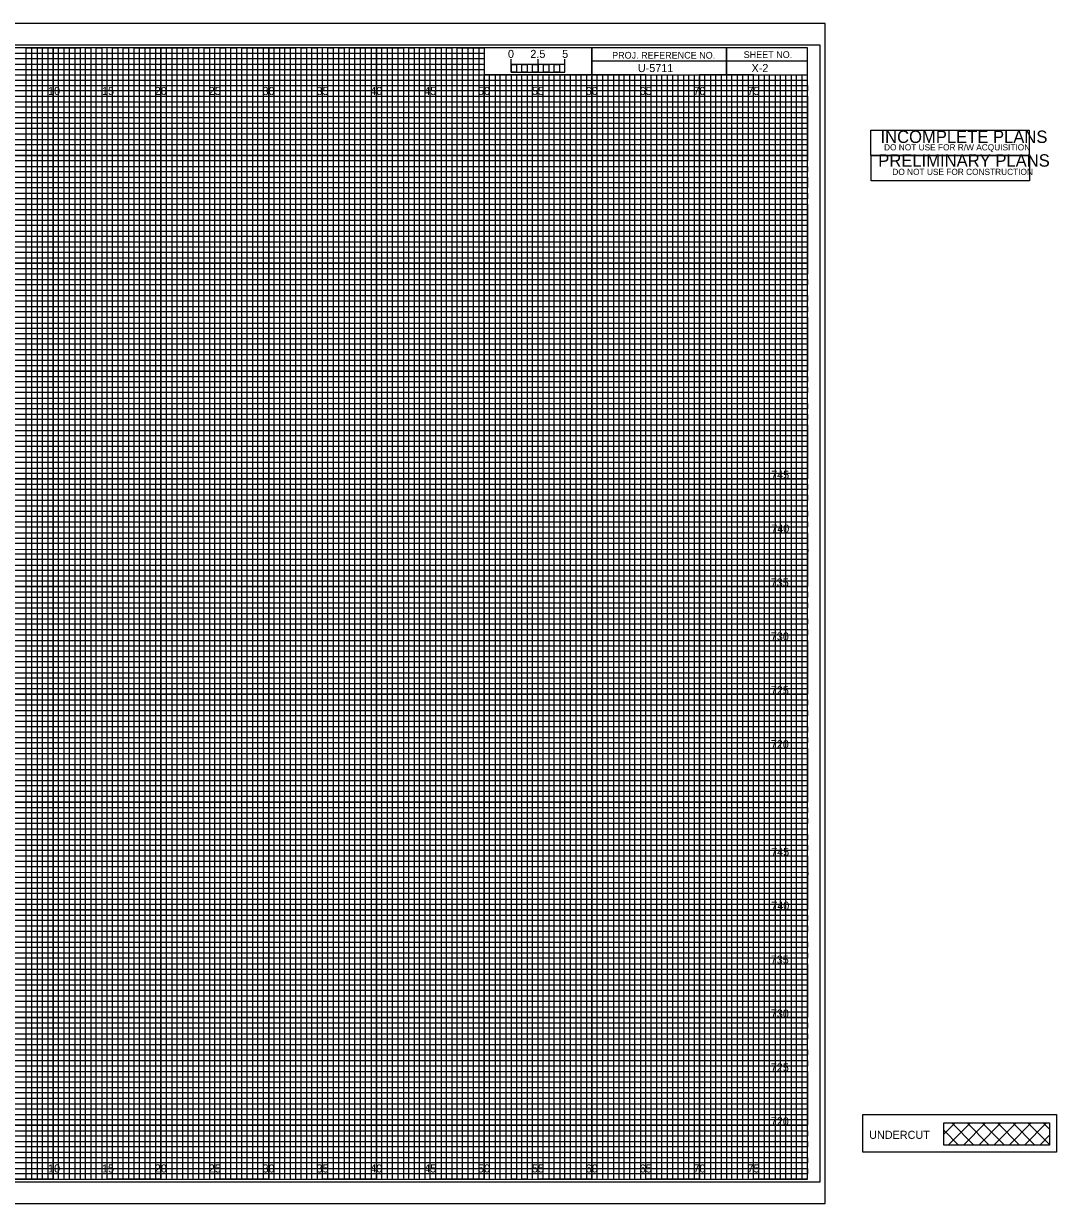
# Model space of a CAD drawing. Extents: x -7 to 183, y -2 to 107.
# Drawn here: x 87.2 to 183.1, y -2.2 to 107.2 of the extents above; entities that cross this region are included whole.
import ezdxf

# ---------------------------------------------------------------- set-up
doc = ezdxf.new("R2010")
doc.units = 0
for name, color, linetype in [('Prop Grid Mask', 7, 'Continuous'), ('Prop Road Sect_ Recs - UC (Outline)', 7, 'Continuous'), ('Prop VPI Label', 7, 'Continuous'), ('Prop XS Bar Scale Labels', 7, 'Continuous'), ('Prop XS Elevation Labels', 7, 'Continuous'), ('Prop XS Offset Labels', 7, 'Continuous'), ('Prop XS Project Number', 7, 'Continuous'), ('Prop XS Sheet Number', 7, 'Continuous'), ('Sheet Cross Section CELL', 7, 'Continuous'), ('Sheet Cross Section Grid Major CELL', 7, 'Continuous'), ('Sheet Cross Section Grid Middle CELL', 7, 'Continuous'), ('Sheet Cross Section Grid Minor 1 CELL', 7, 'Continuous'), ('Sheet Cross Section Grid Minor 2 CELL', 7, 'Continuous'), ('Sheet Cross Section Scale CELL', 7, 'Continuous'), ('Sheet Cutting Line CELL', 7, 'Continuous'), ('Sheet DOT Grid CELL', 7, 'Continuous'), ('Sheet Plot Border Inside CELL', 7, 'Continuous'), ('Sheet Plot Border Outside CELL', 7, 'Continuous'), ('Sheet Sticker Incomplete CELL', 7, 'Continuous'), ('Sheet Sticker Preliminary CELL', 7, 'Continuous')]:
    doc.layers.add(name, color=color, linetype=linetype)

msp = doc.modelspace()

# ---------------------------------------------------------------- linework, layer by layer
at = {"layer": 'Prop Grid Mask'}
msp.add_lwpolyline([(165.14, 5.99), (183.12, 5.99), (183.12, 2.5), (165.14, 2.5)], close=True, dxfattribs=at)
at = {"layer": 'Prop Road Sect_ Recs - UC (Outline)'}
for p, q in [((172.66, 4.17), (173.71, 5.22)), ((172.66, 4.56), (174.04, 3.17)), ((173.08, 3.17), (175.13, 5.22)), ((173.41, 5.22), (175.46, 3.17)), ((174.49, 3.17), (176.54, 5.22)), ((174.83, 5.22), (176.87, 3.17)), ((175.91, 3.17), (177.95, 5.22)), ((176.24, 5.22), (178.29, 3.17)), ((177.32, 3.17), (179.37, 5.22)), ((177.65, 5.22), (179.7, 3.17)), ((178.74, 3.17), (180.78, 5.22)), ((179.07, 5.22), (181.11, 3.17)), ((180.15, 3.17), (182.2, 5.22)), ((180.48, 5.22), (182.47, 3.23)), ((181.9, 5.22), (182.47, 4.64)), ((181.57, 3.17), (182.47, 4.08))]:
    msp.add_line(p, q, dxfattribs=at)
msp.add_lwpolyline([(172.66, 5.22), (182.47, 5.22), (182.47, 3.17), (172.66, 3.17)], close=True, dxfattribs=at)
at = {"layer": 'Sheet Cross Section CELL'}
for p, q in [((152.5, 105), (152.5, 102.5)), ((152.5, 102.5), (152.5, 105)), ((160, 103.75), (140, 103.75)), ((140, 103.75), (140, 102.5)), ((140, 102.5), (160, 102.5))]:
    msp.add_line(p, q, dxfattribs=at)
for points in [[(160, 105), (0, 105), (0, 0), (160, 0)], [(140, 105), (130, 105), (130, 102.52), (140, 102.52)], [(160, 105), (140, 105), (140, 102.5), (160, 102.5)]]:
    msp.add_lwpolyline(points, close=True, dxfattribs=at)
at = {"layer": 'Sheet Cross Section Grid Major CELL'}
for p, q in [((95, 105), (90, 105)), ((90, 105), (90, 0)), ((95, 0), (95, 105)), ((105, 105), (100, 105)), ((100, 105), (100, 0)), ((105, 0), (105, 105)), ((115, 105), (110, 105)), ((110, 105), (110, 0)), ((115, 0), (115, 105)), ((125, 105), (120, 105)), ((120, 105), (120, 0)), ((125, 0), (125, 105)), ((130, 105), (130, 0)), ((135, 0), (135, 102.5)), ((145, 102.5), (140, 102.5)), ((140, 102.5), (140, 0)), ((145, 0), (145, 102.5)), ((155, 102.5), (150, 102.5)), ((150, 102.5), (150, 0)), ((155, 0), (155, 102.5)), ((90, 0), (85, 0)), ((100, 0), (95, 0)), ((110, 0), (105, 0)), ((120, 0), (115, 0)), ((130, 0), (125, 0)), ((140, 0), (135, 0)), ((150, 0), (145, 0)), ((160, 0), (155, 0)), ((160, 0), (160, 0))]:
    msp.add_line(p, q, dxfattribs=at)
for points in [[(0, 100), (160, 100), (160, 95), (0, 95)], [(0, 90), (160, 90), (160, 85), (0, 85)], [(0, 80), (160, 80), (160, 75), (0, 75)], [(0, 70), (160, 70), (160, 65), (0, 65)], [(0, 60), (160, 60), (160, 55), (0, 55)], [(0, 50), (160, 50), (160, 45), (0, 45)], [(0, 40), (160, 40), (160, 35), (0, 35)], [(0, 30), (160, 30), (160, 25), (0, 25)], [(0, 20), (160, 20), (160, 15), (0, 15)], [(0, 10), (160, 10), (160, 5), (0, 5)]]:
    msp.add_lwpolyline(points, dxfattribs=at)
at = {"layer": 'Sheet Cross Section Grid Middle CELL'}
for points in [[(82.5, 0), (87.5, 0), (87.5, 105), (92.5, 105), (92.5, 0), (97.5, 0), (97.5, 105), (102.5, 105), (102.5, 0), (107.5, 0), (107.5, 105), (112.5, 105), (112.5, 0), (117.5, 0), (117.5, 105), (122.5, 105), (122.5, 0), (127.5, 0), (127.5, 105), (129.97, 105), (130, 105), (130, 102.5), (132.5, 102.5), (132.5, 0), (137.5, 0), (137.5, 102.5), (142.5, 102.5), (142.5, 0), (147.5, 0), (147.5, 102.5), (152.5, 102.5), (152.5, 0), (157.5, 0), (157.5, 102.5)], [(0, 102.5), (137.5, 102.5)], [(0, 92.5), (160, 92.5), (160, 97.5), (0, 97.5)], [(0, 82.5), (160, 82.5), (160, 87.5), (0, 87.5)], [(0, 72.5), (160, 72.5), (160, 77.5), (0, 77.5)], [(0, 62.5), (160, 62.5), (160, 67.5), (0, 67.5)], [(0, 52.5), (160, 52.5), (160, 57.5), (0, 57.5)], [(0, 42.5), (160, 42.5), (160, 47.5), (0, 47.5)], [(0, 32.5), (160, 32.5), (160, 37.5), (0, 37.5)], [(0, 22.5), (160, 22.5), (160, 27.5), (0, 27.5)], [(0, 12.5), (160, 12.5), (160, 17.5), (0, 17.5)], [(0, 2.5), (160, 2.5), (160, 7.5), (0, 7.5)]]:
    msp.add_lwpolyline(points, dxfattribs=at)
at = {"layer": 'Sheet Cross Section Grid Minor 1 CELL'}
for p, q in [((0, 104.5), (130, 104.5)), ((130, 104.5), (130, 103.99)), ((130, 103.99), (0, 103.99)), ((0, 103.5), (130, 103.5)), ((130, 102.95), (0, 102.95)), ((130, 103.5), (130, 102.95)), ((0, 102), (160, 102))]:
    msp.add_line(p, q, dxfattribs=at)
for points in [[(0, 101.5), (135, 101.5), (160, 101.5), (160, 101), (0, 101)], [(0, 100.5), (160, 100.5), (160, 99.5), (0, 99.5)], [(0, 99), (160, 99), (160, 98.5), (0, 98.49)], [(0, 98), (160, 98), (160, 97), (0, 97)], [(0, 96.5), (160, 96.5), (160, 96), (0, 96)], [(0, 95.5), (160, 95.5), (160, 94.5), (0, 94.5)], [(0, 94), (160, 94), (160, 93.5), (0, 93.5)], [(0, 93), (160, 93), (160, 92), (0, 92)], [(0, 91.5), (160, 91.5), (160, 91), (0, 91)], [(0, 90.5), (160, 90.5), (160, 89.5), (0, 89.5)], [(0, 89), (160, 89), (160, 88.5), (0, 88.5)], [(0, 88), (160, 88), (160, 86.98), (160, 86.5), (160, 86), (0, 86)], [(0, 87), (160, 87), (160, 86.5), (0, 86.5)], [(0, 85.5), (160, 85.5), (160, 84.5), (0, 84.52)], [(0, 84.52), (160, 84.5), (160, 84), (0, 84)], [(0, 83.5), (160, 83.5), (160, 83), (0, 83)], [(0, 82), (160, 82), (160, 81.5), (0, 81.5)], [(0, 81), (160, 81), (160, 80.5), (0, 80.5)], [(-0.04, 79.45), (160, 79.45), (160, 78.94), (-0.04, 78.94)], [(0, 78.5), (160, 78.5), (160, 78), (0, 78)], [(0, 77), (160, 77), (160, 76.5), (0, 76.5)], [(0, 76), (160, 76), (160, 75.5), (0, 75.5)], [(0, 74.5), (160, 74.5), (160, 74), (0, 74)], [(0, 73.5), (160, 73.5), (160, 73), (0, 73)], [(0, 72), (160, 72), (160, 71.5), (0, 71.5)], [(0, 71), (160, 71), (160, 70.5), (0, 70.5)], [(0, 69.5), (160, 69.5), (160, 68.99), (0, 69)], [(0, 68.5), (160, 68.5), (160, 68), (0, 68)], [(0, 67), (160, 67), (160, 66.5), (0, 66.5)], [(0, 66), (160, 66), (160, 65.5), (0, 65.5)], [(0, 64.5), (160, 64.5), (160, 64), (0, 64)], [(0, 63.5), (160, 63.5), (160, 63), (0, 63)], [(0, 62), (160, 62), (160, 61.5), (0, 61.5)], [(0, 61), (160, 61), (160, 60.5), (0, 60.5)], [(0, 59.5), (160, 59.5), (160, 59), (0, 59)], [(0, 58.5), (160.03, 58.45), (160, 58), (0, 58)], [(0, 57), (160, 57), (160, 56.5), (0, 56.5)], [(0, 56), (160, 56), (160, 55.5), (0, 55.5)], [(0, 54.5), (160, 54.5), (160, 54), (0, 54)], [(0, 53.5), (160, 53.5), (160, 53), (0, 53)], [(0, 52), (160, 52), (160, 51.5), (0, 51.5)], [(0, 51), (160, 51), (160, 50.5), (0, 50.5)], [(0, 49.5), (160, 49.5), (160, 49), (0, 49)], [(0, 48.5), (160, 48.5), (160, 48), (0, 48)], [(0, 47), (160, 47), (160, 46.5), (0, 46.5)], [(0, 46), (160, 46), (160, 45.5), (0, 45.5)], [(0, 44.5), (160, 44.5), (160, 44), (0, 44)], [(0, 43.5), (160, 43.5), (160, 43), (0, 43)], [(0, 42), (160, 42), (160, 41.5), (0, 41.5)], [(0, 41), (160, 41), (160, 40.5), (0, 40.5)], [(0, 39.5), (160, 39.5), (160, 38.99), (0, 39)], [(0, 38.5), (160, 38.5), (160, 38), (0, 38)], [(0, 37), (160, 37), (160, 36.5), (0, 36.5)], [(0, 36), (160, 36), (160, 35.5), (0, 35.5)], [(0, 34.5), (160, 34.5), (160, 34), (0, 34)], [(0, 33.5), (160, 33.5), (160, 33), (0, 33)], [(0, 32), (160, 32), (160, 31.5), (0, 31.5)], [(0, 31), (160, 31), (160, 30.5), (0, 30.5)], [(0, 29.5), (160, 29.5), (160, 29), (0, 29)], [(0, 28.5), (160.03, 28.46), (160, 28), (0, 28)], [(0, 27), (160, 27), (160, 26.5), (0, 26.5)], [(0, 26), (160, 26), (160, 25.5), (0, 25.5)], [(0, 24.5), (160, 24.5), (160, 24), (0, 24)], [(0, 23.5), (160, 23.5), (160, 23), (0, 23)], [(0, 22), (160, 22), (160, 21.5), (0, 21.5)], [(0, 21), (160, 21), (160, 20.5), (0, 20.5)], [(0, 19.5), (160, 19.5), (160, 19), (0, 19)], [(0, 18.5), (160, 18.5), (160, 18), (0, 18)], [(0, 17), (160, 17), (160, 16.5), (0, 16.5)], [(0, 16), (160, 16), (160, 15.5), (0, 15.5)], [(0, 14.5), (160, 14.5), (160, 14), (0, 14)], [(0, 13.5), (160, 13.5), (160, 13), (0, 13)], [(0, 12), (160, 12), (160, 11.5), (0, 11.5)], [(0, 11), (160, 11), (160, 10.5), (0, 10.5)], [(0, 9.5), (160, 9.5), (160, 9), (0, 9)], [(0, 8.5), (160, 8.5), (160, 8), (0, 8)], [(0, 7), (160, 7), (160, 6.5), (0, 6.5)], [(0, 6), (160, 6), (160, 5.5), (0, 5.5)], [(0, 4.5), (160, 4.5), (160, 4), (0, 4)], [(0, 3.5), (160, 3.5), (160, 3), (0, 3)], [(0, 2), (160, 2), (160, 1.5), (0, 1.5)], [(0, 1), (160, 1), (160, 0.5), (0, 0.5)]]:
    msp.add_lwpolyline(points, dxfattribs=at)
at = {"layer": 'Sheet Cross Section Grid Minor 2 CELL'}
for p, q in [((133.5, 102.5), (133, 102.5)), ((133, 102.5), (133, 0)), ((133.5, 0), (133.5, 102.5)), ((134.5, 102.5), (134, 102.5)), ((134, 102.5), (134, 0)), ((134.5, 0), (134.5, 102.5)), ((133, 0), (132.5, 0)), ((134, 0), (133.5, 0))]:
    msp.add_line(p, q, dxfattribs=at)
for points in [[(87.5, 0), (88, 0), (88, 105), (88.5, 105), (88.5, 0)], [(88.5, 0), (89, 0), (89, 105), (89.5, 105), (89.5, 0)], [(90, 0), (90.5, 0), (90.5, 105), (91, 105), (91, 0)], [(91, 0), (91.5, 0), (91.5, 105), (92, 105), (92, 0)], [(92.5, 0), (93, 0), (93, 105), (93.5, 105), (93.5, 0)], [(93.5, 0), (94, 0), (94, 105), (94.5, 105), (94.5, 0)], [(95, 0), (95.5, 0), (95.5, 105), (96, 105), (96, 0)], [(96, 0), (96.5, 0), (96.5, 105), (97, 105), (97, 0)], [(97.5, 0), (98, 0), (98, 105), (98.5, 105), (98.5, 0)], [(98.5, 0), (99, 0), (99, 105), (99.5, 105), (99.5, 0)], [(100, 0), (100.5, 0), (100.5, 105), (101, 105), (101, 0)], [(101, 0), (101.5, 0), (101.5, 105), (102, 105), (102, 0)], [(102.5, 0), (103, 0), (103, 105), (103.5, 105), (103.5, 0)], [(103.5, 0), (104, 0), (104, 105), (104.5, 105), (104.5, 0)], [(105, 0), (105.5, 0), (105.5, 105), (106, 105), (106, 0)], [(106, 0), (106.5, 0), (106.5, 105), (107, 105), (107, 0)], [(107.5, 0), (108, 0), (108, 105), (108.5, 105), (108.5, 0)], [(108.5, 0), (109, 0), (109, 105), (109.5, 105), (109.5, 0)], [(110, 0), (110.5, 0), (110.5, 105), (111, 105), (111, 0)], [(111, 0), (111.5, 0), (111.5, 105), (112, 105), (112, 0)], [(112.5, 0), (113, 0), (113, 105), (113.5, 105), (113.5, 0)], [(113.5, 0), (114, 0), (114, 105), (114.5, 105), (114.5, 0)], [(115, 0), (115.5, 0), (115.5, 105), (116, 105), (116, 0)], [(116, 0), (116.5, 0), (116.5, 105), (117, 105), (117, 0)], [(117.5, 0), (118, 0), (118, 105), (118.5, 105), (118.5, 0)], [(118.5, 0), (119, 0), (119, 105), (119.5, 105), (119.5, 0)], [(120, 0), (120.5, 0), (120.5, 105), (121, 105), (121, 0)], [(121, 0), (121.5, 0), (121.5, 105), (122, 105), (122, 0)], [(122.5, 0), (123, 0), (123, 105), (123.5, 105), (123.5, 0)], [(123.5, 0), (124, 0), (124, 105), (124.5, 105), (124.5, 0)], [(125, 0), (125.5, 0), (125.5, 105), (126, 105), (126, 0)], [(126, 0), (126.5, 0), (126.5, 105), (127, 105), (127, 0)], [(127.5, 0), (128, 0), (128, 105), (128.5, 105), (128.5, 0)], [(128.5, 0), (129, 0), (129, 105), (129.5, 105), (129.5, 0)], [(130, 0), (130.5, 0), (130.5, 102.5), (131.01, 102.5), (131.01, 0)], [(131, 0), (131.5, 0), (131.5, 102.5), (132, 102.5), (132, 0)], [(135, 0), (135.49, 0), (135.49, 102.5), (136, 102.5), (136, 0)], [(136, 0), (136.5, 0), (136.5, 102.5), (137.03, 102.5), (137.03, 0)], [(137.5, 0), (138, 0), (138, 102.5), (138.5, 102.5), (138.5, 0)], [(138.5, 0), (139, 0), (139, 102.5), (139.5, 102.5), (139.5, 0)], [(140, 0), (140.5, 0), (140.5, 102.5), (141, 102.5), (141, 0)], [(141, 0), (141.5, 0), (141.5, 102.5), (142, 102.5), (142, 0)], [(142.5, 0), (143, 0), (143, 102.5), (143.5, 102.5), (143.5, 0)], [(143.5, 0), (144, 0), (144, 102.5), (144.5, 102.5), (144.5, 0)], [(145, 0), (145.5, 0), (145.5, 102.5), (146, 102.5), (146, 0)], [(146, 0), (146.5, 0), (146.5, 102.5), (147, 102.5), (147, 0)], [(147.5, 0), (148, 0), (148, 102.5), (148.5, 102.5), (148.5, 0)], [(148.5, 0), (149, 0), (149, 102.5), (149.5, 102.5), (149.5, 0)], [(150, 0), (150.5, 0), (150.5, 102.5), (151, 102.5), (151, 0)], [(151, 0), (151.5, 0), (151.5, 102.5), (152, 102.5), (152, 0)], [(152.5, 0), (153, 0), (153, 102.5), (153.5, 102.5), (153.5, 0)], [(153.5, 0), (154, 0), (154, 102.5), (154.5, 102.5), (154.5, 0)], [(155, 0), (155.5, 0), (155.5, 102.5), (156, 102.5), (156, 0)], [(156, 0), (156.5, 0), (156.5, 102.5), (157, 102.5), (157, 0)], [(157.5, 0), (158, 0), (158, 102.5), (158.5, 102.5), (158.5, 0)], [(158.5, 0), (159, 0), (159, 102.5), (159.5, 102.5), (159.5, 0)]]:
    msp.add_lwpolyline(points, dxfattribs=at)
at = {"layer": 'Sheet Cross Section Scale CELL'}
for p, q in [((132.5, 102.75), (132.5, 103.95)), ((132.5, 103.45), (132.5, 103.95)), ((135, 102.75), (135, 103.95)), ((137.5, 102.75), (137.5, 103.95)), ((137.5, 103.45), (137.5, 103.95))]:
    msp.add_line(p, q, dxfattribs=at)
for points in [[(137.5, 103.45), (132.5, 103.45), (132.5, 102.75), (137.5, 102.75)], [(132.5, 103.45), (133, 103.45), (133, 102.75), (132.5, 102.75)], [(133.5, 103.45), (134, 103.45), (134, 102.75), (133.5, 102.75)], [(134.5, 103.45), (135, 103.45), (135, 102.75), (134.5, 102.75)], [(135.5, 103.45), (136, 103.45), (136, 102.75), (135.5, 102.75)], [(136.5, 103.45), (137, 103.45), (137, 102.75), (136.5, 102.75)]]:
    msp.add_lwpolyline(points, close=True, dxfattribs=at)
at = {"layer": 'Sheet Cutting Line CELL'}
for p, q in [((161.65, 107.25), (-6.7, 107.25)), ((-6.7, -2.25), (161.65, -2.25))]:
    msp.add_line(p, q, dxfattribs=at)
at = {"layer": 'Sheet DOT Grid CELL'}
for p, q in [((90, 0), (90, 105)), ((95, 0), (95, 105)), ((100, 0), (100, 105)), ((105, 0), (105, 105)), ((110, 0), (110, 105)), ((115, 0), (115, 105)), ((120, 0), (120, 105)), ((125, 0), (125, 105)), ((130, 0), (130, 102.34)), ((135, 0), (135, 102.34)), ((140, 0), (140, 102.34)), ((145, 0), (145, 102.34)), ((150, 0), (150, 102.34)), ((155, 0), (155, 102.34)), ((0, 100), (160, 100)), ((0, 95), (160, 95)), ((0, 90), (160, 90)), ((0, 85), (160, 85)), ((0, 80), (160, 80)), ((0, 75), (160, 75)), ((0, 70), (160, 70)), ((0, 65), (160, 65)), ((0, 60), (160, 60)), ((0, 55), (160, 55)), ((0, 50), (160, 50)), ((0, 45), (160, 45)), ((0, 40), (160, 40)), ((0, 35), (160, 35)), ((0, 30), (160, 30)), ((0, 25), (160, 25)), ((0, 20), (160, 20)), ((0, 15), (160, 15)), ((0, 10), (160, 10)), ((0, 5), (160, 5))]:
    msp.add_line(p, q, dxfattribs=at)
at = {"layer": 'Sheet Plot Border Inside CELL'}
msp.add_lwpolyline([(-5.4, -0.25), (161.2, -0.25), (161.2, 105.25), (-5.4, 105.25)], close=True, dxfattribs=at)
at = {"layer": 'Sheet Plot Border Outside CELL'}
msp.add_lwpolyline([(-6.7, -2.25), (161.65, -2.25), (161.65, 107.25), (-6.7, 107.25)], close=True, dxfattribs=at)
at = {"layer": 'Sheet Sticker Incomplete CELL'}
msp.add_lwpolyline([(165.9, 95), (165.9, 97.35), (180.6, 97.35), (180.6, 95)], close=True, dxfattribs=at)
at = {"layer": 'Sheet Sticker Preliminary CELL'}
msp.add_lwpolyline([(165.93, 92.65), (165.93, 95), (180.63, 95), (180.63, 92.65)], close=True, dxfattribs=at)

# ---------------------------------------------------------------- texts
at = {"layer": 'Prop VPI Label'}
msp.add_text('UNDERCUT', height=0.75, dxfattribs=at).set_placement((165.74, 3.74))
at = {"layer": 'Prop XS Bar Scale Labels'}
for s, p in [('2.5', (134.29, 104.06)), ('5', (137.24, 104.06))]:
    msp.add_text(s, height=0.75, dxfattribs=at).set_placement(p)
at = {"layer": 'Prop XS Elevation Labels'}
for s, p in [('745', (156.64, 65)), ('740', (156.65, 60)), ('735', (156.6, 55)), ('730', (156.61, 50)), ('725', (156.61, 45)), ('720', (156.61, 40)), ('745', (156.64, 30)), ('740', (156.65, 25)), ('735', (156.6, 20)), ('730', (156.61, 15)), ('725', (156.61, 10)), ('720', (156.61, 5))]:
    msp.add_text(s, height=0.75, dxfattribs=at).set_placement(p)
at = {"layer": 'Prop XS Offset Labels'}
for s, p in [('10', (89.52, 100.62)), ('15', (94.53, 100.62)), ('20', (99.43, 100.62)), ('25', (104.44, 100.62)), ('30', (109.43, 100.62)), ('35', (114.44, 100.62)), ('40', (119.43, 100.62)), ('45', (124.44, 100.62)), ('50', (129.43, 100.62)), ('55', (134.44, 100.62)), ('60', (139.43, 100.62)), ('65', (144.44, 100.62)), ('70', (149.43, 100.62)), ('75', (154.44, 100.62)), ('10', (89.52, 0.62)), ('15', (94.53, 0.62)), ('20', (99.43, 0.62)), ('25', (104.44, 0.62)), ('30', (109.43, 0.62)), ('35', (114.44, 0.62)), ('40', (119.43, 0.62)), ('45', (124.44, 0.62)), ('50', (129.43, 0.62)), ('55', (134.44, 0.62)), ('60', (139.43, 0.62)), ('65', (144.44, 0.62)), ('70', (149.43, 0.62)), ('75', (154.44, 0.62))]:
    msp.add_text(s, height=0.75, dxfattribs=at).set_placement(p)
at = {"layer": 'Prop XS Project Number'}
msp.add_text('U-5711', height=0.75, dxfattribs=at).set_placement((144.27, 102.75))
at = {"layer": 'Prop XS Sheet Number'}
msp.add_text('X-2', height=0.75, dxfattribs=at).set_placement((154.82, 102.75))
at = {"layer": 'Sheet Cross Section CELL'}
for s, p in [('PROJ. REFERENCE NO.', (141.88, 104)), ('SHEET NO.', (154.09, 104.06))]:
    msp.add_text(s, height=0.625, dxfattribs=at).set_placement(p)
at = {"layer": 'Sheet Cross Section Scale CELL'}
msp.add_text('0', height=0.75, dxfattribs=at).set_placement((132.21, 104.06))
at = {"layer": 'Sheet Sticker Incomplete CELL'}
for s, height, p in [('INCOMPLETE PLANS', 1.152, (166.79, 96.17)), ('DO NOT USE FOR R/W ACQUISITION', 0.576, (167.12, 95.48))]:
    msp.add_text(s, height=height, dxfattribs=at).set_placement(p)
at = {"layer": 'Sheet Sticker Preliminary CELL'}
for s, height, p in [('PRELIMINARY PLANS', 1.152, (166.58, 93.97)), ('DO NOT USE FOR CONSTRUCTION', 0.576, (167.89, 93.2))]:
    msp.add_text(s, height=height, dxfattribs=at).set_placement(p)

doc.saveas('drawing.dxf')
